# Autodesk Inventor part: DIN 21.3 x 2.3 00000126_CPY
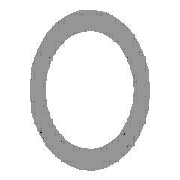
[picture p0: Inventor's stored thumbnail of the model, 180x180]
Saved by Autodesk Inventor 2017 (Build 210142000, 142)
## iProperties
Created: 2017-11
Part Number: DIN 21.3 x 2.3 00000126_CPY
Material: Steel, Mild
Description: Pipe
Document SubType Name: Modeling
Standard: DIN
Designer: iusti
Standard Revision: 2006-07
Standards Organization: DIN
Language: en-US
Size Designation: 21.3 x 2.3
Categories: <MemberInstance><Categories><Category DisplayName="Structural Shapes" InternalName="089c4875-fa83-4c05-b084-43b9cc11f5ed" Mnemonic="GRDR"><CategoryParameter Dis
Stock Number: 21.3 x 2.3
Density: 7.85 g/cm^3
Appearance: Semi-Polished
_CCFamilyMember: 1
_CCFamilyDisplayName: DIN EN 10210-2 - Pipe
_FrameMemberDoc: Frame Member File
_Version: 15.0.0
_GetPNFromCC: 1
IsCustomPart: 1
Author: iusti
G_L: 2570.401 mm
G_W: 21.300 mm
G_H: 21.300 mm
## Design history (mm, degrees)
node "Start plane"
node "End plane"
sketch "Sketch"
  geometry: C1 r 8.35 at (0, 0); C2 r 10.65 at (0, 0); 2 further points
  constraints: 3 coincident, 2 centre point
  dimensions: "d0" = 21.3 diameter of C2 (= G_H); "d1" = 2.3 radial gap between concentric circles of C2 C1 (= G_T)
extrude "Body" new body sketch "Sketch" stored distance "d2" = 2570.40077 (= G_L); taper "d3" = 0 deg
node "Driven Length"
  sketch "Sketch3"
    geometry: L1 (0, 0)-(10, 0) reference
    constraints: 2 end point, 1 horizontal
  workplane "Work Plane3"
  sketch "Sketch4"
    geometry: L1 (-2, 0)-(12, 0) reference; L2 (-2, 2570.401)-(12, 2570.401) reference
    dimensions: "d7" = 2570.40077 distance between parallel lines of L1 L2 (derived)
body "Solid1"
other parameters: "G_H" = 21.3 [user parameter; used in 1 equation term], "G_T" = 2.3 [user parameter; used in 1 equation term], "G_L" = 2570.40077 (= d7) [user parameter; used in 1 equation term], "G_OFFSET_START" = 0 [user parameter; used in 1 equation term], "G_OFFSET_END" = 0 [user parameter; used in 1 equation term], "d4" = 0 (computed from G_OFFSET_START), "d5" = 2570.40077 (= G_OFFSET_END + B_L), "B_L" = 2570.40077 [user parameter; used in 1 equation term], "d6" = 90 deg
